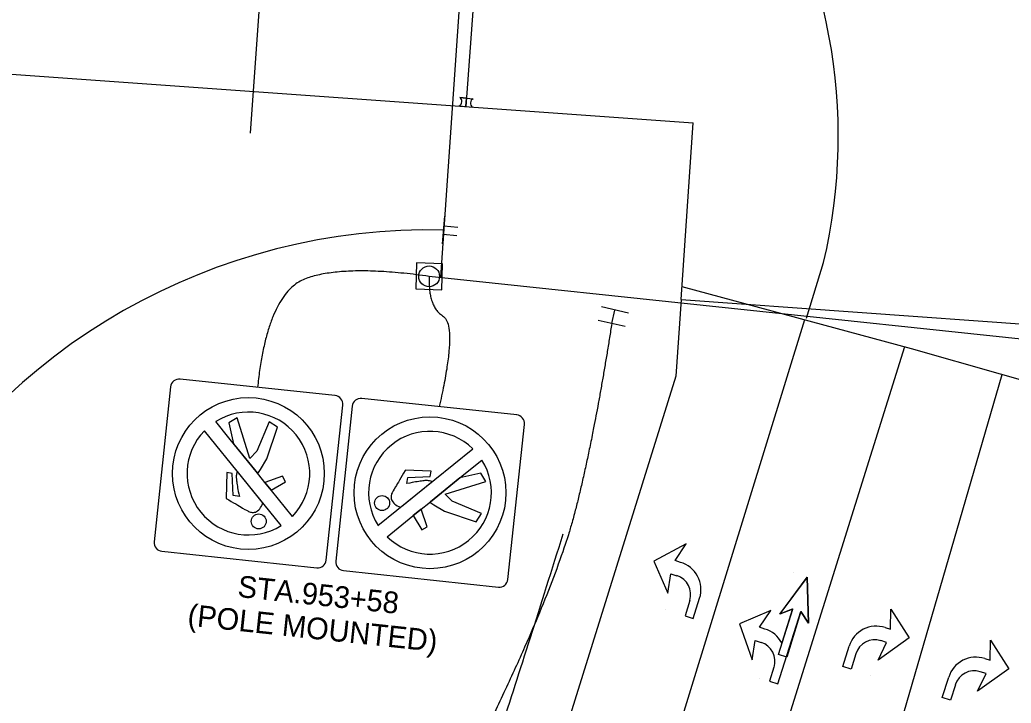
# Model space of a CAD drawing. Extents: x 1847379 to 1850904, y 217032 to 220169.
# Drawn here: x 1849441.6 to 1849556.2, y 218709.4 to 218788.3 of the extents above; entities that cross this region are included whole.
import ezdxf

# ---------------------------------------------------------------- set-up
doc = ezdxf.new("R2010")
doc.units = 0
for name, color, linetype in [('BR_P_Gen_Approach_Slab_Hidden', 7, 'Continuous'), ('BR_P_Gen_Phase_Construction', 7, 'Continuous'), ('PM_P_Cells', 7, 'Continuous'), ('PM_P_Dotted_Line', 7, 'Continuous'), ('PM_P_Edge_Line', 7, 'Continuous'), ('PM_P_Stop_Line', 7, 'Continuous'), ('PM_X_Cells', 7, 'Continuous'), ('PM_X_Channelizing_Line', 7, 'Continuous'), ('PM_X_Stop_Line', 7, 'Continuous'), ('SG_X_Wiring', 7, 'Continuous'), ('SN_X_Foundation', 7, 'Continuous'), ('SN_X_Public', 7, 'Continuous'), ('SN_X_Text', 7, 'Continuous')]:
    doc.layers.add(name, color=color, linetype=linetype)

msp = doc.modelspace()

# ---------------------------------------------------------------- linework, layer by layer
at = {"layer": 'BR_P_Gen_Approach_Slab_Hidden'}
for p, q in [((1849518.03, 218755.98), (1849517.42, 218747.13)), ((1849517.42, 218747.13), (1849500.81, 218693.84))]:
    msp.add_line(p, q, dxfattribs=at)
at = {"layer": 'BR_P_Gen_Phase_Construction'}
for p, q in [((1849474.12, 218857.66), (1849468.24, 218775.2)), ((1849518.03, 218755.98), (1849584.7, 218751.23))]:
    msp.add_line(p, q, dxfattribs=at)
at = {"layer": 'PM_P_Cells'}
for p, q in [((1849493.24, 218779.25), (1849492.47, 218779.32)), ((1849492.47, 218779.32), (1849493.24, 218779.25)), ((1849493.15, 218778.28), (1849493.24, 218779.25)), ((1849493.24, 218779.25), (1849494.01, 218779.18)), ((1849492.39, 218778.35), (1849493.15, 218778.28)), ((1849492.39, 218778.35), (1849493.15, 218778.28)), ((1849493.15, 218778.28), (1849493.92, 218778.21)), ((1849532.6, 218723.91), (1849529.43, 218719.67)), ((1849531.01, 218724.42), (1849531.01, 218724.42)), ((1849532.74, 218718.62), (1849532.6, 218723.91)), ((1849528.4, 218720.06), (1849524.77, 218718.53)), ((1849527.09, 218718.13), (1849528.4, 218720.06)), ((1849529.21, 218711.61), (1849531.86, 218719.95)), ((1849529.43, 218719.67), (1849530.91, 218720.25)), ((1849531.86, 218719.95), (1849532.74, 218718.62)), ((1849524.77, 218718.53), (1849526.24, 218714.37)), ((1849527.72, 218717.93), (1849527.09, 218718.13)), ((1849526.24, 218714.37), (1849526.6, 218716.61)), ((1849526.6, 218716.61), (1849527.27, 218716.39)), ((1849528.77, 218713.51), (1849528.26, 218711.91)), ((1849527.15, 218712.27), (1849527.15, 218712.27)), ((1849528.26, 218711.91), (1849529.21, 218711.61))]:
    msp.add_line(p, q, dxfattribs=at)
msp.add_lwpolyline([(1849530.91, 218720.25), (1849529.67, 218716.34)], dxfattribs=at)
for centre, radius, start, end in [((1849492.13, 218778.86), 0.576, 296.8063, 52.8586), ((1849492.13, 218778.86), 0.576, 296.8063, 52.8586), ((1849494.27, 218778.67), 0.576, 116.8063, 232.8586), ((1849526.78, 218714.79), 3.28, 28.3375, 73.2926), ((1849526.58, 218714.2), 2.3, 342.3841, 72.3841)]:
    msp.add_arc(centre, radius, start, end, dxfattribs=at)
at = {"layer": 'PM_P_Dotted_Line'}
msp.add_line((1849532.54, 218753.84), (1849534.5, 218760.25), dxfattribs=at)
msp.add_arc((1849472.91, 218774.84), 63.29, 346.672, 82.3018, dxfattribs=at)
at = {"layer": 'PM_P_Edge_Line'}
for p in [(1848953.55, 218816.79), (1849518.03, 218755.98)]:
    msp.add_line(p, (1849519.44, 218776.41), dxfattribs=at)
at = {"layer": 'PM_P_Stop_Line'}
msp.add_line((1849494.9, 218802.22), (1849493.15, 218778.28), dxfattribs=at)
at = {"layer": 'PM_X_Cells'}
for p, q in [((1849518.64, 218727.77), (1849514.87, 218725.76)), ((1849518.64, 218727.77), (1849514.87, 218725.76)), ((1849517.34, 218725.83), (1849518.64, 218727.77)), ((1849517.34, 218725.83), (1849518.64, 218727.77)), ((1849518.64, 218727.77), (1849518.64, 218727.77)), ((1849518.64, 218727.77), (1849518.64, 218727.77)), ((1849514.87, 218725.76), (1849516.52, 218722.06)), ((1849514.87, 218725.76), (1849516.52, 218722.06)), ((1849517.98, 218725.63), (1849517.34, 218725.83)), ((1849517.98, 218725.63), (1849517.34, 218725.83)), ((1849516.52, 218722.06), (1849516.86, 218724.3)), ((1849516.52, 218722.06), (1849516.86, 218724.3)), ((1849516.86, 218724.3), (1849517.53, 218724.09)), ((1849516.86, 218724.3), (1849517.53, 218724.09)), ((1849529.45, 218719.66), (1849532.6, 218723.91)), ((1849532.6, 218723.91), (1849532.6, 218723.91)), ((1849532.6, 218723.91), (1849532.77, 218718.62)), ((1849519.44, 218719.14), (1849520.18, 218721.5)), ((1849519.44, 218719.14), (1849520.18, 218721.5)), ((1849519.04, 218721.21), (1849518.49, 218719.44)), ((1849519.04, 218721.21), (1849518.49, 218719.44)), ((1849516.26, 218720.13), (1849516.26, 218720.13)), ((1849516.26, 218720.13), (1849516.26, 218720.13)), ((1849518.49, 218719.44), (1849519.44, 218719.14)), ((1849518.49, 218719.44), (1849519.44, 218719.14)), ((1849529.29, 218714.99), (1849530.93, 218720.24)), ((1849530.93, 218720.24), (1849529.45, 218719.66)), ((1849531.88, 218719.95), (1849530.25, 218714.7)), ((1849532.77, 218718.62), (1849531.88, 218719.95)), ((1849542.25, 218717.9), (1849542.28, 218720.24)), ((1849542.25, 218717.9), (1849542.28, 218720.24)), ((1849542.28, 218720.24), (1849542.28, 218720.24)), ((1849542.28, 218720.24), (1849544.38, 218716.9)), ((1849542.28, 218720.24), (1849542.28, 218720.24)), ((1849542.28, 218720.24), (1849544.38, 218716.9)), ((1849541.61, 218718.1), (1849542.25, 218717.9)), ((1849541.61, 218718.1), (1849542.25, 218717.9)), ((1849544.38, 218716.9), (1849540.79, 218714.34)), ((1849544.38, 218716.9), (1849540.79, 218714.34)), ((1849536.72, 218713.6), (1849537.46, 218715.96)), ((1849536.72, 218713.6), (1849537.46, 218715.96)), ((1849540.79, 218714.34), (1849541.77, 218716.38)), ((1849540.79, 218714.34), (1849541.77, 218716.38)), ((1849541.77, 218716.38), (1849541.1, 218716.59)), ((1849541.77, 218716.38), (1849541.1, 218716.59)), ((1849553.75, 218714.32), (1849553.78, 218716.66)), ((1849553.75, 218714.32), (1849553.78, 218716.66)), ((1849553.78, 218716.66), (1849553.78, 218716.66)), ((1849553.78, 218716.66), (1849555.89, 218713.32)), ((1849553.78, 218716.66), (1849553.78, 218716.66)), ((1849553.78, 218716.66), (1849555.89, 218713.32)), ((1849530.25, 218714.7), (1849529.29, 218714.99)), ((1849529.77, 218714.85), (1849529.77, 218714.85)), ((1849538.23, 218715.08), (1849537.67, 218713.3)), ((1849538.23, 218715.08), (1849537.67, 218713.3)), ((1849537.67, 218713.3), (1849536.72, 218713.6)), ((1849537.67, 218713.3), (1849536.72, 218713.6)), ((1849553.12, 218714.52), (1849553.75, 218714.32)), ((1849553.12, 218714.52), (1849553.75, 218714.32)), ((1849539.9, 218712.6), (1849539.9, 218712.6)), ((1849539.9, 218712.6), (1849539.9, 218712.6)), ((1849548.22, 218710.01), (1849548.96, 218712.38)), ((1849548.22, 218710.01), (1849548.96, 218712.38)), ((1849555.89, 218713.32), (1849552.29, 218710.75)), ((1849555.89, 218713.32), (1849552.29, 218710.75)), ((1849552.29, 218710.75), (1849553.28, 218712.79)), ((1849552.29, 218710.75), (1849553.28, 218712.79)), ((1849553.28, 218712.79), (1849552.61, 218713)), ((1849553.28, 218712.79), (1849552.61, 218713)), ((1849549.73, 218711.49), (1849549.18, 218709.71)), ((1849549.73, 218711.49), (1849549.18, 218709.71)), ((1849549.18, 218709.71), (1849548.22, 218710.01)), ((1849549.18, 218709.71), (1849548.22, 218710.01))]:
    msp.add_line(p, q, dxfattribs=at)
for centre, radius, start, end in [((1849517.05, 218722.48), 3.28, 342.6847, 73.5932), ((1849517.05, 218722.48), 3.28, 342.6847, 73.5932), ((1849516.85, 218721.9), 2.3, 342.6847, 72.6847), ((1849516.85, 218721.9), 2.3, 342.6847, 72.6847), ((1849540.59, 218714.98), 3.28, 71.7762, 162.6847), ((1849540.59, 218714.98), 3.28, 71.7762, 162.6847), ((1849540.42, 218714.39), 2.3, 72.6847, 162.6847), ((1849540.42, 218714.39), 2.3, 72.6847, 162.6847), ((1849552.09, 218711.4), 3.28, 71.7762, 162.6847), ((1849552.09, 218711.4), 3.28, 71.7762, 162.6847), ((1849551.92, 218710.81), 2.3, 72.6847, 162.6847), ((1849551.92, 218710.81), 2.3, 72.6847, 162.6847)]:
    msp.add_arc(centre, radius, start, end, dxfattribs=at)
at = {"layer": 'PM_X_Channelizing_Line'}
for points in [[(1849532.3, 218753.65), (1849512.53, 218689.53), (1849492.16, 218643.5), (1849455.1, 218581.32), (1849423.31, 218533.88), (1849422.33, 218532.18), (1849391.57, 218486.81), (1849363.72, 218433.84)], [(1849543.85, 218750.54), (1849523.2, 218684.58), (1849501.55, 218635.29), (1849465.6, 218575.53), (1849432.35, 218525.21), (1849402.87, 218481.04), (1849375.64, 218428.2)], [(1849386.41, 218422.68), (1849398.05, 218448.32), (1849427.84, 218496.92), (1849472.39, 218563.54), (1849502.15, 218611.88), (1849514.47, 218634.91), (1849523.63, 218654.01), (1849541.52, 218700.42), (1849555.12, 218747.32)]]:
    msp.add_lwpolyline(points, dxfattribs=at)
at = {"layer": 'PM_X_Stop_Line'}
msp.add_lwpolyline([(1849575.51, 218741.51), (1849544.66, 218750.3), (1849518.15, 218757.47)], dxfattribs=at)
at = {"layer": 'SG_X_Wiring'}
for p, q in [((1849490.27, 218758.57), (1849498.1, 218870.79)), ((1849593, 218747.62), (1849488.92, 218758.66))]:
    msp.add_line(p, q, dxfattribs=at)
at = {"layer": 'SN_X_Foundation'}
msp.add_lwpolyline([(1849490.37, 218757.11), (1849490.47, 218760.11), (1849487.47, 218760.22), (1849487.37, 218757.22)], close=True, dxfattribs=at)
msp.add_circle((1849488.92, 218758.66), 1.2, dxfattribs=at)
at = {"layer": 'SN_X_Public'}
for p, q in [((1849490.46, 218762.42), (1849490.72, 218765.6)), ((1849490.59, 218764.01), (1849490.59, 218764.01)), ((1849490.63, 218764.49), (1849492.22, 218764.36)), ((1849490.55, 218763.53), (1849492.14, 218763.4)), ((1849511.94, 218754.42), (1849508.82, 218755.13)), ((1849510.02, 218753.21), (1849510.38, 218754.77)), ((1849511.58, 218752.86), (1849508.46, 218753.57)), ((1849510.2, 218753.99), (1849510.2, 218753.99)), ((1849466.74, 218742.33), (1849465.78, 218741.75)), ((1849466.74, 218742.33), (1849465.78, 218741.75)), ((1849468.22, 218737.63), (1849466.74, 218742.33)), ((1849468.22, 218737.63), (1849466.74, 218742.33)), ((1849465.78, 218741.75), (1849466.33, 218739.33)), ((1849465.78, 218741.75), (1849466.33, 218739.33)), ((1849470.44, 218741.85), (1849469.02, 218738.46)), ((1849470.44, 218741.85), (1849469.02, 218738.46)), ((1849470.18, 218737.57), (1849471.41, 218741.24)), ((1849470.18, 218737.57), (1849471.41, 218741.24)), ((1849471.41, 218741.24), (1849470.44, 218741.85)), ((1849471.41, 218741.24), (1849470.44, 218741.85)), ((1849471.81, 218729.88), (1849462.96, 218740.84)), ((1849466.33, 218739.33), (1849469.08, 218735.94)), ((1849483.01, 218729.9), (1849493.97, 218738.75)), ((1849469.02, 218738.46), (1849468.22, 218737.63)), ((1849469.02, 218738.46), (1849468.22, 218737.63)), ((1849469.45, 218736.35), (1849470.18, 218737.57)), ((1849469.45, 218736.35), (1849470.18, 218737.57)), ((1849469.13, 218735.88), (1849469.45, 218736.35)), ((1849469.13, 218735.88), (1849469.45, 218736.35)), ((1849465.54, 218736.02), (1849465.45, 218733.02)), ((1849465.54, 218736.02), (1849465.45, 218733.02)), ((1849466.17, 218735.9), (1849465.54, 218736.02)), ((1849466.17, 218735.9), (1849465.54, 218736.02)), ((1849466.27, 218733.34), (1849466.17, 218735.9)), ((1849466.27, 218733.34), (1849466.17, 218735.9)), ((1849469.63, 218732.58), (1849466.77, 218736.12)), ((1849469.08, 218735.94), (1849469.13, 218735.88)), ((1849471.99, 218735.57), (1849469.95, 218734.87)), ((1849471.99, 218735.57), (1849469.95, 218734.87)), ((1849472.34, 218734.94), (1849471.99, 218735.57)), ((1849472.34, 218734.94), (1849471.99, 218735.57)), ((1849489.15, 218736.17), (1849486.15, 218736.26)), ((1849486.15, 218736.26), (1849486.15, 218736.24)), ((1849489.15, 218736.17), (1849486.15, 218736.26)), ((1849486.15, 218736.26), (1849486.15, 218736.24)), ((1849486.36, 218734.72), (1849486.47, 218735.44)), ((1849486.36, 218734.72), (1849486.47, 218735.44)), ((1849486.47, 218735.44), (1849489.03, 218735.54)), ((1849486.47, 218735.44), (1849489.03, 218735.54)), ((1849489.03, 218735.54), (1849489.15, 218736.17)), ((1849489.03, 218735.54), (1849489.15, 218736.17)), ((1849492.46, 218735.38), (1849489.07, 218732.63)), ((1849494.88, 218735.93), (1849492.46, 218735.38)), ((1849494.88, 218735.93), (1849492.46, 218735.38)), ((1849495.46, 218734.97), (1849494.88, 218735.93)), ((1849495.46, 218734.97), (1849494.88, 218735.93)), ((1849469.95, 218734.87), (1849470.09, 218734.68)), ((1849470.68, 218733.96), (1849472.34, 218734.94)), ((1849470.68, 218733.96), (1849472.34, 218734.94)), ((1849485.71, 218732.08), (1849489.25, 218734.94)), ((1849490.76, 218733.49), (1849495.46, 218734.97)), ((1849490.76, 218733.49), (1849495.46, 218734.97)), ((1849465.45, 218733.02), (1849465.47, 218733.02)), ((1849465.45, 218733.02), (1849465.47, 218733.02)), ((1849466.99, 218733.23), (1849466.27, 218733.34)), ((1849466.99, 218733.23), (1849466.27, 218733.34)), ((1849491.58, 218732.69), (1849490.76, 218733.49)), ((1849491.58, 218732.69), (1849490.76, 218733.49)), ((1849469.72, 218732.46), (1849469.63, 218732.58)), ((1849485.59, 218731.99), (1849485.71, 218732.08)), ((1849487.99, 218731.76), (1849487.81, 218731.62)), ((1849488.69, 218729.72), (1849487.99, 218731.76)), ((1849488.69, 218729.72), (1849487.99, 218731.76)), ((1849489.07, 218732.63), (1849489, 218732.58)), ((1849489, 218732.58), (1849489.48, 218732.26)), ((1849489, 218732.58), (1849489.48, 218732.26)), ((1849489.48, 218732.26), (1849490.7, 218731.53)), ((1849489.48, 218732.26), (1849490.7, 218731.53)), ((1849494.98, 218731.27), (1849491.58, 218732.69)), ((1849494.98, 218731.27), (1849491.58, 218732.69)), ((1849487.09, 218731.03), (1849488.07, 218729.37)), ((1849487.09, 218731.03), (1849488.07, 218729.37)), ((1849490.7, 218731.53), (1849494.37, 218730.3)), ((1849490.7, 218731.53), (1849494.37, 218730.3)), ((1849494.37, 218730.3), (1849494.98, 218731.27)), ((1849494.37, 218730.3), (1849494.98, 218731.27)), ((1849488.07, 218729.37), (1849488.69, 218729.72)), ((1849488.07, 218729.37), (1849488.69, 218729.72))]:
    msp.add_line(p, q, dxfattribs=at)
for points in [[(1849478.04, 218744.9), (1849460.14, 218746.8)], [(1849459.04, 218745.91), (1849457.14, 218728.01)], [(1849499.04, 218742.67), (1849481.14, 218744.57)], [(1849477.03, 218725.9), (1849478.93, 218743.8)], [(1849480.04, 218743.68), (1849478.14, 218725.78)], [(1849470.09, 218734.68), (1849469.08, 218735.94), (1849465.78, 218740.01), (1849464.26, 218741.89)], [(1849498.03, 218723.67), (1849499.93, 218741.57)], [(1849487.81, 218731.62), (1849489.07, 218732.63), (1849493.14, 218735.93), (1849495.02, 218737.45)], [(1849473.12, 218730.94), (1849470.71, 218733.92), (1849470.09, 218734.68), (1849470.09, 218734.68)], [(1849470.09, 218734.68), (1849470.68, 218733.96), (1849470.68, 218733.96)], [(1849469.63, 218732.58), (1849469.63, 218732.58)], [(1849485.71, 218732.08), (1849485.71, 218732.08)], [(1849484.07, 218728.59), (1849487.05, 218731), (1849487.81, 218731.62), (1849487.81, 218731.62)], [(1849487.81, 218731.62), (1849487.09, 218731.03), (1849487.09, 218731.03)], [(1849458.03, 218726.91), (1849475.93, 218725.01)], [(1849479.03, 218724.68), (1849496.93, 218722.78)]]:
    msp.add_lwpolyline(points, dxfattribs=at)
for centre, radius in [((1849468.04, 218735.89), 8.77), ((1849489.02, 218733.67), 8.77), ((1849483.49, 218732.48), 0.864), ((1849469.23, 218730.36), 0.864)]:
    msp.add_circle(centre, radius, dxfattribs=at)
for centre, radius, start, end in [((1849488.85, 218692.79), 71.24, 88.6045, 150.6957), ((1849460.04, 218745.8), 1, 83.9415, 173.9415), ((1849477.94, 218743.9), 1, 353.9415, 83.9415), ((1849481.03, 218743.57), 1, 83.9415, 173.9415), ((1849468.04, 218735.89), 7.09, 315.7894, 122.1894), ((1849468.04, 218735.89), 7.09, 315.7894, 122.1894), ((1849498.93, 218741.67), 1, 353.9415, 83.9415), ((1849468.04, 218735.89), 7.09, 135.7606, 302.1128), ((1849489.02, 218733.67), 7.09, 45.7606, 212.1128), ((1849489.02, 218733.67), 7.09, 225.7894, 32.1894), ((1849489.02, 218733.67), 7.09, 225.7894, 32.1894), ((1849458.14, 218727.9), 1, 173.9415, 263.9415), ((1849476.04, 218726), 1, 263.9415, 353.9415), ((1849479.13, 218725.67), 1, 173.9415, 263.9415), ((1849497.03, 218723.77), 1, 263.9415, 353.9415)]:
    msp.add_arc(centre, radius, start, end, dxfattribs=at)
for points in [[(1849466.77, 218736.12), (1849466.73, 218736.05), (1849466.64, 218735.86), (1849466.63, 218735.4), (1849466.67, 218734.98), (1849466.79, 218734.24), (1849466.89, 218733.72), (1849466.99, 218733.23)], [(1849466.77, 218736.12), (1849466.73, 218736.05), (1849466.64, 218735.86), (1849466.63, 218735.4), (1849466.67, 218734.98), (1849466.79, 218734.24), (1849466.89, 218733.72), (1849466.99, 218733.23)], [(1849486.15, 218736.24), (1849485.67, 218735.4), (1849484.89, 218734.09), (1849484.61, 218733.61), (1849484.56, 218733.44), (1849484.54, 218733.28), (1849484.5, 218732.88), (1849484.92, 218732.33), (1849485.33, 218732.12), (1849485.59, 218731.99)], [(1849486.15, 218736.24), (1849485.67, 218735.4), (1849484.89, 218734.09), (1849484.61, 218733.61), (1849484.56, 218733.44), (1849484.54, 218733.28), (1849484.5, 218732.88), (1849484.92, 218732.33), (1849485.33, 218732.12), (1849485.59, 218731.99)], [(1849489.25, 218734.94), (1849489.18, 218734.98), (1849488.98, 218735.07), (1849488.52, 218735.08), (1849488.1, 218735.04), (1849487.36, 218734.92), (1849486.85, 218734.82), (1849486.36, 218734.72)], [(1849489.25, 218734.94), (1849489.18, 218734.98), (1849488.98, 218735.07), (1849488.52, 218735.08), (1849488.1, 218735.04), (1849487.36, 218734.92), (1849486.85, 218734.82), (1849486.36, 218734.72)], [(1849465.47, 218733.02), (1849466.31, 218732.54), (1849467.62, 218731.76), (1849468.1, 218731.48), (1849468.27, 218731.43), (1849468.43, 218731.41), (1849468.83, 218731.37), (1849469.38, 218731.79), (1849469.59, 218732.21), (1849469.72, 218732.46)], [(1849465.47, 218733.02), (1849466.31, 218732.54), (1849467.62, 218731.76), (1849468.1, 218731.48), (1849468.27, 218731.43), (1849468.43, 218731.41), (1849468.83, 218731.37), (1849469.38, 218731.79), (1849469.59, 218732.21), (1849469.72, 218732.46)]]:
    msp.add_open_spline(points, degree=3, dxfattribs=at)
at = {"layer": 'SN_X_Text'}
for points in [[(1849494.67, 218818.75), (1849500.66, 218818.68), (1849506.53, 218812.81), (1849502.68, 218794.1), (1849444.39, 218796.58), (1849429.74, 218793.85), (1849428.09, 218773.83)], [(1849488.92, 218758.66), (1849479.37, 218760.01), (1849470.25, 218756.91), (1849469.09, 218745.85)], [(1849488.92, 218758.66), (1849488.8, 218755.15), (1849492.23, 218752.98), (1849490.09, 218743.62)], [(1849510.02, 218753.21), (1849508.01, 218740.25), (1849503.62, 218723.05), (1849488.22, 218691.24), (1849476.92, 218691.86)], [(1849470.87, 218664.76), (1849480.41, 218661.91), (1849490.53, 218684.65), (1849504.41, 218728.93)]]:
    msp.add_open_spline(points, degree=2, dxfattribs=at)

# ---------------------------------------------------------------- texts
for s, p in [('STA.953+58', (1849466.71, 218721.65)), ('(POLE MOUNTED)', (1849460.93, 218718.34))]:
    msp.add_text(s, height=2.5, rotation=353.9415, dxfattribs=at).set_placement(p)

doc.saveas('drawing.dxf')
